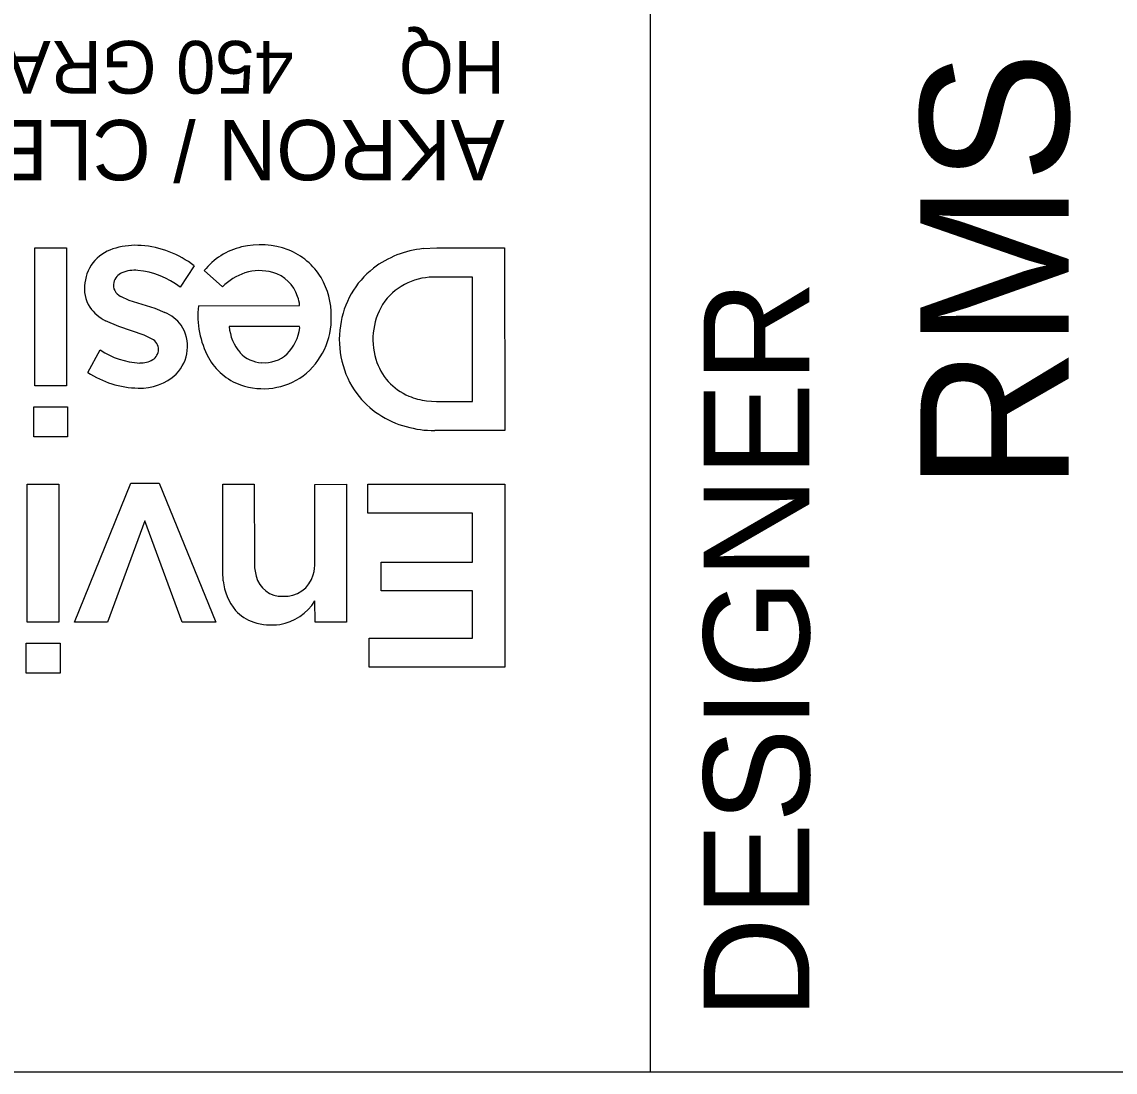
# Model space of a CAD drawing. Extents: x 2392589 to 2394670, y 184794 to 185659.
# Drawn here: x 2392967.39 to 2392988.06, y 185619.17 to 185639.03 of the extents above; entities that cross this region are included whole.
import ezdxf

# ---------------------------------------------------------------- set-up
doc = ezdxf.new("R2010")
doc.units = 0
doc.layers.add('MD_P_Surface_Asphalt_Concrete_Surface_Course', color=7, linetype='Continuous')
doc.layers.add('MD_P_Surface_Finished_Grade_Seeded', color=7, linetype='Continuous')

msp = doc.modelspace()

# ---------------------------------------------------------------- linework, layer by layer
at = {"layer": 'MD_P_Surface_Asphalt_Concrete_Surface_Course'}
for p, q in [((2392967.635, 185632.15), (2392967.635, 185634.756)), ((2392967.635, 185634.756), (2392968.233, 185634.756)), ((2392968.233, 185634.756), (2392968.233, 185632.15)), ((2392974.98, 185634.742), (2392975.237, 185634.756)), ((2392975.237, 185634.756), (2392976.519, 185634.756)), ((2392976.519, 185634.756), (2392976.52, 185631.301)), ((2392970.651, 185634.415), (2392970.386, 185634.012)), ((2392971.186, 185634.018), (2392970.839, 185634.326)), ((2392975.913, 185634.202), (2392975.232, 185634.203)), ((2392975.912, 185631.854), (2392975.913, 185634.202)), ((2392969.259, 185633.841), (2392969.413, 185633.769)), ((2392969.413, 185633.769), (2392969.903, 185633.615)), ((2392970.73, 185633.663), (2392972.64, 185633.665)), ((2392969.903, 185633.615), (2392970.095, 185633.537)), ((2392969.228, 185633.269), (2392968.974, 185633.38)), ((2392969.706, 185633.107), (2392969.228, 185633.269)), ((2392972.643, 185633.27), (2392971.313, 185633.27)), ((2392972.646, 185633.245), (2392972.643, 185633.27)), ((2392969.856, 185633.032), (2392969.706, 185633.107)), ((2392968.638, 185632.403), (2392968.874, 185632.826)), ((2392968.233, 185632.15), (2392967.635, 185632.15)), ((2392975.044, 185631.866), (2392975.233, 185631.854)), ((2392975.233, 185631.854), (2392975.912, 185631.854)), ((2392967.616, 185631.183), (2392967.616, 185631.75)), ((2392967.616, 185631.75), (2392968.257, 185631.75)), ((2392968.257, 185631.75), (2392968.257, 185631.183)), ((2392968.257, 185631.183), (2392967.616, 185631.183)), ((2392976.52, 185631.301), (2392975.199, 185631.301)), ((2392967.494, 185627.681), (2392967.494, 185630.287)), ((2392967.494, 185630.287), (2392968.091, 185630.287)), ((2392968.091, 185630.287), (2392968.091, 185627.681)), ((2392968.387, 185627.681), (2392969.453, 185630.307)), ((2392969.453, 185630.307), (2392969.991, 185630.307)), ((2392969.991, 185630.307), (2392971.062, 185627.681)), ((2392971.191, 185628.63), (2392971.191, 185630.287)), ((2392971.191, 185630.287), (2392971.786, 185630.287)), ((2392971.786, 185630.287), (2392971.788, 185628.8)), ((2392972.933, 185630.286), (2392973.528, 185630.287)), ((2392972.933, 185628.817), (2392972.933, 185630.286)), ((2392973.528, 185630.287), (2392973.53, 185627.681)), ((2392973.935, 185629.744), (2392973.935, 185630.287)), ((2392973.935, 185630.287), (2392976.521, 185630.287)), ((2392976.521, 185630.287), (2392976.521, 185626.832)), ((2392975.914, 185629.744), (2392973.935, 185629.744)), ((2392975.914, 185628.816), (2392975.914, 185629.744)), ((2392969.72, 185629.596), (2392969.014, 185627.681)), ((2392970.421, 185627.681), (2392969.72, 185629.596)), ((2392974.182, 185628.273), (2392974.182, 185628.816)), ((2392974.182, 185628.816), (2392975.914, 185628.816)), ((2392971.2, 185628.46), (2392971.191, 185628.63)), ((2392972.934, 185627.681), (2392972.933, 185628.083)), ((2392975.914, 185628.273), (2392974.182, 185628.273)), ((2392975.914, 185627.375), (2392975.914, 185628.273)), ((2392968.091, 185627.681), (2392967.494, 185627.681)), ((2392969.014, 185627.681), (2392968.387, 185627.681)), ((2392971.062, 185627.681), (2392970.421, 185627.681)), ((2392973.53, 185627.681), (2392972.934, 185627.681)), ((2392967.474, 185626.714), (2392967.474, 185627.281)), ((2392967.474, 185627.281), (2392968.116, 185627.281)), ((2392968.116, 185627.281), (2392968.116, 185626.714)), ((2392973.96, 185626.832), (2392973.96, 185627.375)), ((2392973.96, 185627.375), (2392975.914, 185627.375)), ((2392968.116, 185626.714), (2392967.474, 185626.714)), ((2392976.521, 185626.832), (2392973.96, 185626.832))]:
    msp.add_line(p, q, dxfattribs=at)
for points in [[(2392968.233, 185632.15), (2392967.635, 185632.15), (2392967.635, 185634.756), (2392968.233, 185634.756)], [(2392968.257, 185631.183), (2392967.616, 185631.183), (2392967.616, 185631.75), (2392968.257, 185631.75)], [(2392968.091, 185627.681), (2392967.494, 185627.681), (2392967.494, 185630.287), (2392968.091, 185630.287)], [(2392971.062, 185627.681), (2392970.421, 185627.681), (2392969.72, 185629.596), (2392969.014, 185627.681), (2392968.387, 185627.681), (2392969.453, 185630.307), (2392969.991, 185630.307)], [(2392976.521, 185626.832), (2392973.96, 185626.832), (2392973.96, 185627.375), (2392975.914, 185627.375), (2392975.914, 185628.273), (2392974.182, 185628.273), (2392974.182, 185628.816), (2392975.914, 185628.816), (2392975.914, 185629.744), (2392973.935, 185629.744), (2392973.935, 185630.287), (2392976.521, 185630.287)], [(2392968.116, 185626.714), (2392967.474, 185626.714), (2392967.474, 185627.281), (2392968.116, 185627.281)]]:
    msp.add_lwpolyline(points, close=True, dxfattribs=at)
for points in [[(2392974.98, 185634.742), (2392975.237, 185634.756), (2392976.519, 185634.756), (2392976.52, 185631.301)], [(2392970.651, 185634.415), (2392970.386, 185634.012)], [(2392971.186, 185634.018), (2392970.839, 185634.326)], [(2392975.044, 185631.866), (2392975.233, 185631.854), (2392975.912, 185631.854), (2392975.913, 185634.202), (2392975.232, 185634.203)], [(2392969.259, 185633.841), (2392969.413, 185633.769), (2392969.903, 185633.615), (2392970.095, 185633.537)], [(2392970.73, 185633.663), (2392972.64, 185633.665)], [(2392969.856, 185633.032), (2392969.706, 185633.107), (2392969.228, 185633.269), (2392968.974, 185633.38)], [(2392972.646, 185633.245), (2392972.643, 185633.27), (2392971.313, 185633.27)], [(2392968.638, 185632.403), (2392968.874, 185632.826)], [(2392976.52, 185631.301), (2392975.199, 185631.301)], [(2392971.2, 185628.46), (2392971.191, 185628.63), (2392971.191, 185630.287), (2392971.786, 185630.287), (2392971.788, 185628.8)], [(2392972.933, 185628.817), (2392972.933, 185630.286), (2392973.528, 185630.287), (2392973.53, 185627.681)], [(2392973.53, 185627.681), (2392972.934, 185627.681), (2392972.933, 185628.083)]]:
    msp.add_lwpolyline(points, dxfattribs=at)
for centre, radius, start, end in [((2392969.387, 185633.93), 0.853, 104.9966, 136.2063), ((2392969.387, 185633.93), 0.853, 104.9966, 136.2063), ((2392969.545, 185633.381), 1.424, 85.8306, 105.3914), ((2392969.545, 185633.381), 1.424, 85.8306, 105.3914), ((2392969.515, 185632.963), 1.844, 51.9777, 85.8738), ((2392969.515, 185632.963), 1.844, 51.9777, 85.8738), ((2392971.846, 185633.521), 1.289, 103.5336, 141.3615), ((2392971.846, 185633.521), 1.289, 103.5336, 141.3615), ((2392971.895, 185633.3), 1.516, 69.3542, 103.3785), ((2392971.895, 185633.3), 1.516, 69.3542, 103.3785), ((2392971.975, 185633.551), 1.252, 30.9427, 68.7323), ((2392971.975, 185633.551), 1.252, 30.9427, 68.7323), ((2392975.166, 185632.89), 1.862, 95.7333, 127.304), ((2392975.166, 185632.89), 1.862, 95.7333, 127.304), ((2392969.315, 185634.028), 0.733, 137.7934, 174.6892), ((2392969.315, 185634.028), 0.733, 137.7934, 174.6892), ((2392969.377, 185634.052), 0.251, 111.5098, 168.5262), ((2392969.377, 185634.052), 0.251, 111.5098, 168.5262), ((2392969.526, 185633.691), 0.642, 84.5726, 112.068), ((2392969.526, 185633.691), 0.642, 84.5726, 112.068), ((2392969.449, 185632.822), 1.514, 51.811, 84.7969), ((2392969.449, 185632.822), 1.514, 51.811, 84.7969), ((2392971.968, 185633.248), 1.097, 109.0357, 135.4406), ((2392971.968, 185633.248), 1.097, 109.0357, 135.4406), ((2392971.885, 185633.386), 0.94, 74.6059, 107.007), ((2392971.885, 185633.386), 0.94, 74.6059, 107.007), ((2392971.936, 185633.621), 0.701, 18.0077, 73.5508), ((2392971.936, 185633.621), 0.701, 18.0077, 73.5508), ((2392975.053, 185633.064), 1.654, 127.8521, 172.402), ((2392975.053, 185633.064), 1.654, 127.8521, 172.402), ((2392969.227, 185633.985), 0.653, 170.1719, 212.5197), ((2392969.227, 185633.985), 0.653, 170.1719, 212.5197), ((2392969.353, 185634.049), 0.229, 166.6609, 245.7053), ((2392969.353, 185634.049), 0.229, 166.6609, 245.7053), ((2392971.831, 185633.482), 1.411, 359.2048, 30.3341), ((2392971.831, 185633.482), 1.411, 359.2048, 30.3341), ((2392975.18, 185633.031), 1.173, 87.4662, 142.2665), ((2392975.18, 185633.031), 1.173, 87.4662, 142.2665), ((2392972.397, 185633.477), 1.677, 173.615, 208.2876), ((2392972.397, 185633.477), 1.677, 173.615, 208.2876), ((2392972.236, 185633.667), 0.404, 359.7003, 24.8711), ((2392972.236, 185633.667), 0.404, 359.7003, 24.8711), ((2392975.307, 185633.028), 1.278, 145.6727, 197.2093), ((2392975.307, 185633.028), 1.278, 145.6727, 197.2093), ((2392969.337, 185634.105), 0.811, 215.5118, 243.4159), ((2392969.337, 185634.105), 0.811, 215.5118, 243.4159), ((2392969.763, 185632.792), 0.815, 38.0877, 65.9874), ((2392969.763, 185632.792), 0.815, 38.0877, 65.9874), ((2392971.869, 185633.423), 1.374, 307.7452, 1.6543), ((2392971.869, 185633.423), 1.374, 307.7452, 1.6543), ((2392969.772, 185632.892), 0.75, 315.9854, 32.4797), ((2392969.772, 185632.892), 0.75, 315.9854, 32.4797), ((2392972.158, 185633.33), 0.847, 184.008, 220.8817), ((2392972.158, 185633.33), 0.847, 184.008, 220.8817), ((2392975.121, 185633.018), 1.728, 171.194, 215.9984), ((2392975.121, 185633.018), 1.728, 171.194, 215.9984), ((2392971.807, 185633.351), 0.846, 315.0619, 352.7974), ((2392971.807, 185633.351), 0.846, 315.0619, 352.7974), ((2392969.762, 185632.841), 0.213, 357.716, 63.7337), ((2392969.762, 185632.841), 0.213, 357.716, 63.7337), ((2392969.701, 185634.076), 1.499, 236.5112, 266.9101), ((2392969.701, 185634.076), 1.499, 236.5112, 266.9101), ((2392969.633, 185633.035), 0.455, 268.4747, 301.0868), ((2392969.633, 185633.035), 0.455, 268.4747, 301.0868), ((2392969.745, 185632.839), 0.23, 302.2368, 358.3777), ((2392969.745, 185632.839), 0.23, 302.2368, 358.3777), ((2392971.898, 185633.22), 1.117, 208.8308, 250.6244), ((2392971.898, 185633.22), 1.117, 208.8308, 250.6244), ((2392971.954, 185633.182), 0.597, 222.9851, 267.179), ((2392971.954, 185633.182), 0.597, 222.9851, 267.179), ((2392971.979, 185633.207), 0.623, 265.0013, 313.283), ((2392971.979, 185633.207), 0.623, 265.0013, 313.283), ((2392975.123, 185632.951), 1.08, 196.1881, 247.3861), ((2392975.123, 185632.951), 1.08, 196.1881, 247.3861), ((2392969.628, 185633.9), 1.795, 236.531, 268.7571), ((2392969.628, 185633.9), 1.795, 236.531, 268.7571), ((2392969.632, 185633.106), 1.001, 267.5366, 312.7932), ((2392969.632, 185633.106), 1.001, 267.5366, 312.7932), ((2392971.957, 185633.381), 1.287, 250.5201, 305.7831), ((2392971.957, 185633.381), 1.287, 250.5201, 305.7831), ((2392975.101, 185633.05), 1.731, 217.2362, 255.148), ((2392975.101, 185633.05), 1.731, 217.2362, 255.148), ((2392975.202, 185633.138), 1.282, 247.3571, 262.9275), ((2392975.202, 185633.138), 1.282, 247.3571, 262.9275), ((2392975.223, 185633.458), 2.157, 254.7861, 269.3704), ((2392975.223, 185633.458), 2.157, 254.7861, 269.3704), ((2392972.708, 185628.794), 0.92, 179.6049, 195.3284), ((2392972.708, 185628.794), 0.92, 179.6049, 195.3284), ((2392972.09, 185628.809), 0.843, 344.0916, 0.5284), ((2392972.09, 185628.809), 0.843, 344.0916, 0.5284), ((2392972.306, 185628.669), 0.5, 193.6865, 272.2187), ((2392972.306, 185628.669), 0.5, 193.6865, 272.2187), ((2392972.368, 185628.719), 0.551, 265.5854, 345.1439), ((2392972.368, 185628.719), 0.551, 265.5854, 345.1439), ((2392972.194, 185628.547), 0.998, 184.9696, 220.2225), ((2392972.194, 185628.547), 0.998, 184.9696, 220.2225), ((2392972.119, 185628.578), 0.952, 278.962, 328.7037), ((2392972.119, 185628.578), 0.952, 278.962, 328.7037), ((2392972.027, 185628.442), 0.803, 222.2219, 251.6818), ((2392972.027, 185628.442), 0.803, 222.2219, 251.6818), ((2392972.116, 185628.747), 1.12, 252.2736, 277.7919), ((2392972.116, 185628.747), 1.12, 252.2736, 277.7919)]:
    msp.add_arc(centre, radius, start, end, dxfattribs=at)
at = {"layer": 'MD_P_Surface_Finished_Grade_Seeded'}
for p, q in [((2392979.279, 185619.173), (2392979.279, 185649.173)), ((2393019.279, 185619.173), (2392599.279, 185619.173))]:
    msp.add_line(p, q, dxfattribs=at)

# ---------------------------------------------------------------- texts
at = {"layer": 'MD_P_Surface_Asphalt_Concrete_Surface_Course'}
for s, height, rotation, p in [('450 GRANT ST., AKRON, OH  44311', 0.99692, 180, (2392972.532, 185638.67)), ('HQ ', 0.9969, 180, (2392976.519, 185638.67)), ('RMS', 2.8, 90, (2392987.179, 185630.155)), ('AKRON / CLEVELAND / COLUMBUS', 1.13938, 180, (2392976.519, 185637.175)), ('DESIGNER', 2, 90, (2392982.279, 185620.173))]:
    msp.add_text(s, height=height, rotation=rotation, dxfattribs=at).set_placement(p)

doc.saveas('drawing.dxf')
